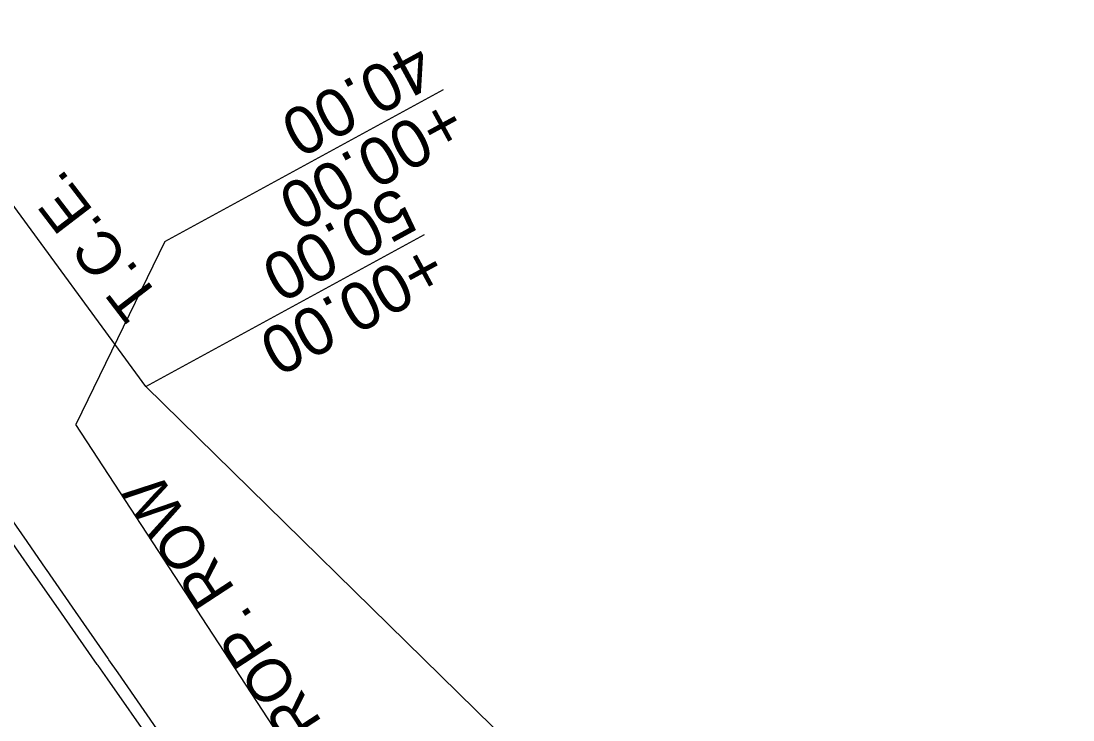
# Model space of a CAD drawing. Extents: x 1627557 to 1636561, y 783843 to 794002.
# Drawn here: x 1627914.8 to 1628047.3, y 785213.4 to 785301.4 of the extents above; entities that cross this region are included whole.
import ezdxf

# ---------------------------------------------------------------- set-up
doc = ezdxf.new("R2010")
doc.units = 0
for name, color, linetype in [('R_Clearzone', 7, 'Continuous'), ('R_Ditch', 7, 'Continuous'), ('R_Proposed Const Limits', 7, 'Continuous'), ('R_ROW', 7, 'Continuous'), ('R_ROW Annot', 7, 'Continuous'), ('R_ROW Annot Labels Ends', 7, 'Continuous'), ('R_Temp Const Easement', 7, 'Continuous'), ('R_Temp Const Easement Annot', 7, 'Continuous'), ('R_Temp Easement Annot', 7, 'Continuous')]:
    doc.layers.add(name, color=color, linetype=linetype)

msp = doc.modelspace()

# ---------------------------------------------------------------- linework, layer by layer
at = {"layer": 'R_Clearzone'}
msp.add_lwpolyline([(1627931.45, 785210.37), (1627925.68, 785218.62), (1627924.51, 785220.29), (1627924.41, 785220.43), (1627920.29, 785226.32), (1627919.91, 785226.86), (1627916.6, 785231.6), (1627916.56, 785231.65), (1627914.14, 785235.11), (1627908.72, 785242.85), (1627908.71, 785242.86), (1627908.68, 785242.91), (1627908.37, 785243.35)], dxfattribs=at)
at = {"layer": 'R_Ditch'}
msp.add_lwpolyline([(1627931.45, 785210.37), (1627925.68, 785218.62), (1627924.51, 785220.29), (1627924.41, 785220.43), (1627920.29, 785226.32), (1627919.91, 785226.86), (1627916.6, 785231.6), (1627916.56, 785231.65), (1627914.14, 785235.11), (1627908.72, 785242.85), (1627908.71, 785242.86), (1627908.68, 785242.91), (1627908.37, 785243.35)], dxfattribs=at)
at = {"layer": 'R_Proposed Const Limits'}
msp.add_lwpolyline([(1627932.76, 785211.08), (1627927.03, 785219.35), (1627925.86, 785221.02), (1627925.76, 785221.17), (1627921.68, 785227.08), (1627921.3, 785227.62), (1627918.01, 785232.37), (1627917.98, 785232.42), (1627915.58, 785235.89), (1627910.15, 785243.63), (1627910.14, 785243.64), (1627910.11, 785243.69), (1627909.78, 785244.12), (1627900.11, 785273.56), (1627905.5, 785284.95), (1627895.98, 785298), (1627859.5, 785301.13)], dxfattribs=at)
at = {"layer": 'R_ROW'}
msp.add_line((1628058.95, 785040.71), (1627921.72, 785250.62), dxfattribs=at)
at = {"layer": 'R_ROW Annot'}
msp.add_line((1627932.91, 785273.67), (1627921.72, 785250.62), dxfattribs=at)
msp.add_lwpolyline([(1627932.91, 785273.67), (1627968.03, 785292.82)], dxfattribs=at)
at = {"layer": 'R_Temp Const Easement'}
for p, q in [((1627930.5, 785255.41), (1627885.81, 785316.47)), ((1628064.95, 785123.71), (1627930.5, 785255.41))]:
    msp.add_line(p, q, dxfattribs=at)
at = {"layer": 'R_Temp Easement Annot'}
msp.add_lwpolyline([(1627930.5, 785255.41), (1627965.61, 785274.56)], dxfattribs=at)

# ---------------------------------------------------------------- texts
at = {"layer": 'R_ROW Annot'}
for s, p in [('40.00', (1627964.67, 785298.96)), ('+00.00', (1627968.5, 785291.94))]:
    msp.add_text(s, height=6, rotation=208.601, dxfattribs=at).set_placement(p)
at = {"layer": 'R_ROW Annot Labels Ends'}
msp.add_text('PROP. ROW', height=5.5, rotation=123.1751, dxfattribs=at).set_placement((1627955.51, 785208.99))
at = {"layer": 'R_Temp Const Easement Annot'}
msp.add_text('T.C.E.', height=5.5, rotation=127.4479, dxfattribs=at).set_placement((1627932.49, 785266.48))
at = {"layer": 'R_Temp Easement Annot'}
for s, p in [('50.00', (1627962.26, 785280.71)), ('+00.00', (1627966.09, 785273.68))]:
    msp.add_text(s, height=6, rotation=208.601, dxfattribs=at).set_placement(p)

doc.saveas('drawing.dxf')
